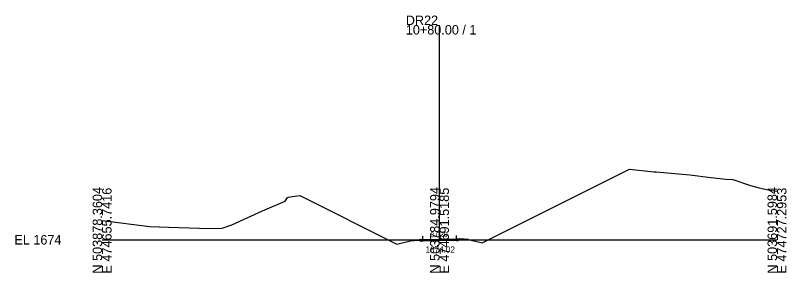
# Model space of a CAD drawing. Extents: x -26 to 1203, y -10 to 9633.
# Drawn here: x -25.7 to 202.8, y 1990.3 to 2066.4 of the extents above; entities that cross this region are included whole.
import ezdxf

# ---------------------------------------------------------------- set-up
doc = ezdxf.new("R2010")
doc.units = 0
for name, color, linetype in [('Exist Cross Section Cell', 7, 'Continuous'), ('Exist XS Center Line Elevation Label', 7, 'Continuous'), ('Exist XS Ground Line', 7, 'Continuous'), ('Prop XS Earthwork Shape', 7, 'Continuous'), ('Prop XS EOT Tick Mark', 7, 'Continuous'), ('Prop XS Finish Grade', 7, 'Continuous'), ('Prop XS Finish Grade Earthwork', 7, 'Continuous'), ('Prop XS Finish Grade Pavement', 7, 'Continuous'), ('Prop XS Pvmt Edge Slope', 7, 'Continuous'), ('Prop XS SE Text', 7, 'Continuous'), ('Prop XS Shoulder Borrow Shape', 7, 'Continuous'), ('Prop XS Subgrade Earthwork', 7, 'Continuous'), ('Scratch_Level_5', 7, 'Continuous')]:
    doc.layers.add(name, color=color, linetype=linetype)

msp = doc.modelspace()

# ---------------------------------------------------------------- linework, layer by layer
at = {"layer": 'Exist Cross Section Cell'}
for p, q in [((100, 2000), (100, 2063.53)), ((0, 2000), (100, 2000)), ((100, 2000), (200, 2000))]:
    msp.add_line(p, q, dxfattribs=at)
at = {"layer": 'Exist XS Ground Line'}
msp.add_lwpolyline([(0, 2005.66), (14.11, 2003.9), (19.69, 2003.74), (31.91, 2003.35), (35.59, 2003.39), (38.47, 2004.46), (47.51, 2008.56), (54.21, 2011.46), (54.94, 2012.56), (55.28, 2012.61), (56.38, 2012.77), (58.61, 2013.09), (87.38, 1998.73), (91.39, 1999.73), (92.37, 1999.81), (93.39, 1999.89), (100, 2000.02), (106.61, 2000.15), (107.63, 2000.11), (108.61, 2000.07), (112.62, 1999.07), (156.26, 2020.85), (163.48, 2020.12), (164.23, 2020.06), (174.2, 2019.18), (180.39, 2018.46), (184.91, 2017.97), (186.92, 2017.85), (192.18, 2016.04), (194.67, 2015.35), (195.62, 2015.15), (197.75, 2014.69), (200, 2014.37)], dxfattribs=at)
at = {"layer": 'Prop XS Earthwork Shape'}
for points in [[(93.98, 2000.03), (91.39, 1999.73), (92.37, 1999.81), (93.39, 1999.89), (94.1, 1999.9)], [(95, 1999.57), (94.45, 1999.56), (94.1, 1999.9), (100, 2000.02), (105.89, 2000.14), (105.53, 1999.78), (105, 1999.77), (100, 1999.67)], [(106.61, 2000.15), (107.63, 2000.11), (108.61, 2000.07), (106.02, 2000.27), (105.89, 2000.14)]]:
    msp.add_lwpolyline(points, close=True, dxfattribs=at)
at = {"layer": 'Prop XS EOT Tick Mark'}
for p, q in [((95, 2000.11), (95, 2001.11)), ((105, 2000.31), (105, 2001.31))]:
    msp.add_line(p, q, dxfattribs=at)
at = {"layer": 'Prop XS Finish Grade'}
for p, q in [((95, 2000.11), (93.98, 2000.03)), ((105, 2000.31), (106.02, 2000.27))]:
    msp.add_line(p, q, dxfattribs=at)
at = {"layer": 'Prop XS Finish Grade Earthwork'}
for p, q in [((93.98, 2000.03), (91.39, 1999.73)), ((106.02, 2000.27), (108.61, 2000.07))]:
    msp.add_line(p, q, dxfattribs=at)
at = {"layer": 'Prop XS Finish Grade Pavement'}
for p, q in [((95, 2000.11), (100, 2000.21)), ((100, 2000.21), (105, 2000.31))]:
    msp.add_line(p, q, dxfattribs=at)
at = {"layer": 'Prop XS Pvmt Edge Slope'}
for p, q in [((95, 2000.11), (94.45, 1999.56)), ((105, 2000.31), (105.53, 1999.78))]:
    msp.add_line(p, q, dxfattribs=at)
at = {"layer": 'Prop XS Shoulder Borrow Shape'}
for points in [[(95, 2000.11), (93.98, 2000.03), (94.45, 1999.56)], [(105, 2000.31), (106.02, 2000.27), (105.53, 1999.78)]]:
    msp.add_lwpolyline(points, close=True, dxfattribs=at)
at = {"layer": 'Prop XS Subgrade Earthwork'}
for p, q in [((94.45, 1999.56), (93.98, 2000.03)), ((100, 1999.67), (95, 1999.57)), ((105, 1999.77), (100, 1999.67)), ((105, 1999.77), (105.53, 1999.78)), ((105.53, 1999.78), (106.02, 2000.27)), ((95, 1999.57), (94.45, 1999.56))]:
    msp.add_line(p, q, dxfattribs=at)
at = {"layer": 'Scratch_Level_5'}
msp.add_lwpolyline([(0, 2005.66), (14.11, 2003.9), (19.69, 2003.74), (31.91, 2003.35), (35.59, 2003.39), (38.47, 2004.46), (47.51, 2008.56), (54.21, 2011.46), (54.94, 2012.56), (55.28, 2012.61), (56.38, 2012.77), (58.61, 2013.09), (87.38, 1998.73), (91.39, 1999.73), (92.37, 1999.81), (93.39, 1999.89), (100, 2000.02), (106.61, 2000.15), (107.63, 2000.11), (108.61, 2000.07), (112.62, 1999.07), (156.26, 2020.85), (163.48, 2020.12), (164.23, 2020.06), (174.2, 2019.18), (180.39, 2018.46), (184.91, 2017.97), (186.92, 2017.85), (192.18, 2016.04), (194.67, 2015.35), (195.62, 2015.15), (197.75, 2014.69), (200, 2014.37)], dxfattribs=at)

# ---------------------------------------------------------------- texts
at = {"layer": 'Exist Cross Section Cell'}
for s, p in [('DR22', (90, 2063.53)), ('10+80.00 / 1', (90, 2060.73)), ('EL 1674', (-26, 1998.6))]:
    msp.add_text(s, height=2.8, dxfattribs=at).set_placement(p)
for s, p in [('N 503878.3604', (0, 1990)), ('E 474655.7416', (2.8, 1990)), ('N 503784.9794', (100, 1990)), ('E 474691.5185', (102.8, 1990)), ('N 503691.5984', (200, 1990)), ('E 474727.2953', (202.8, 1990))]:
    msp.add_text(s, height=2.8, rotation=90, dxfattribs=at).set_placement(p)
at = {"layer": 'Exist XS Center Line Elevation Label'}
msp.add_text('1674.02', height=1.8, dxfattribs=at).set_placement((95.84, 1996.22))
at = {"layer": 'Prop XS SE Text'}
msp.add_text('0.020', height=1.5, rotation=1.1458, dxfattribs=at).set_placement((97.25, 2000.74))

doc.saveas('drawing.dxf')
